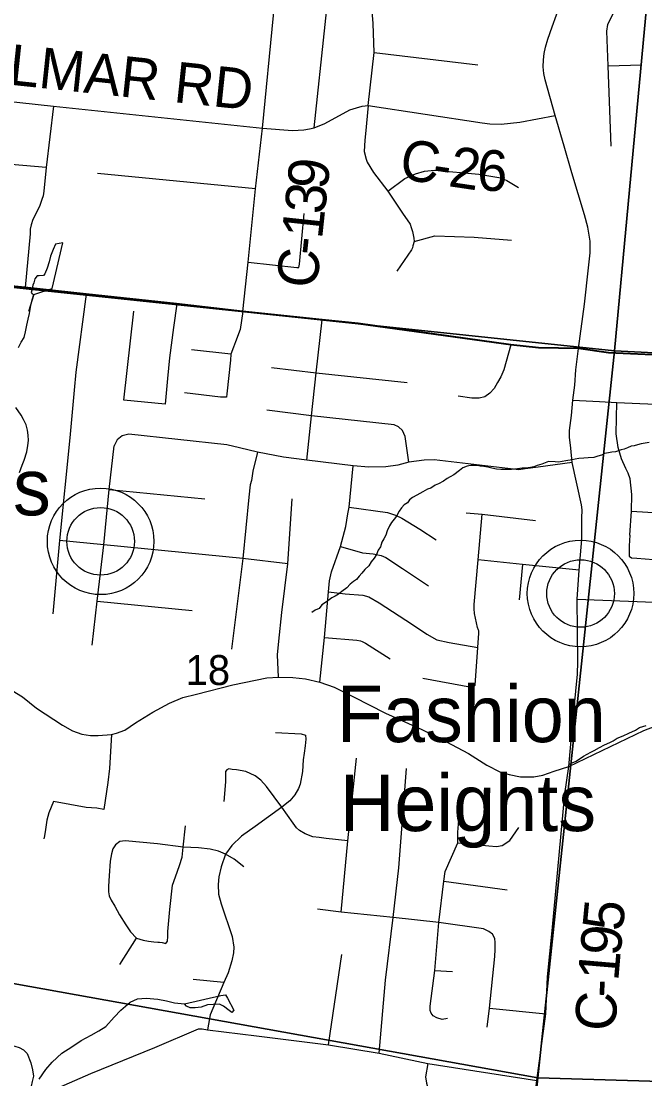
# Model space of a CAD drawing. Extents: x 0 to 34, y -2 to 22.
# Drawn here: x 4.421 to 5.292, y 16.731 to 18.207 of the extents above; entities that cross this region are included whole.
import ezdxf

# ---------------------------------------------------------------- set-up
doc = ezdxf.new("R2010")
doc.units = 0
for name, color, linetype in [('GM_X_City_Street', 7, 'Continuous'), ('GM_X_County_Road', 7, 'Continuous'), ('GM_X_County_Road_Text', 7, 'Continuous'), ('GM_X_Minor_Lake', 7, 'Continuous'), ('GM_X_Minor_River', 7, 'Continuous'), ('GM_X_Rail_Line', 7, 'Continuous'), ('GM_X_Section', 7, 'Continuous'), ('GM_X_Section_Text', 7, 'Continuous'), ('GM_X_Township_Road', 7, 'Continuous'), ('GM_X_Unincorporated', 7, 'Continuous'), ('GM_X_Unincorporated_Location', 7, 'Continuous'), ('GM_X_Unincorporated_Text', 7, 'Continuous')]:
    doc.layers.add(name, color=color, linetype=linetype)

msp = doc.modelspace()

# ---------------------------------------------------------------- linework, layer by layer
at = {"layer": 'GM_X_City_Street'}
for points in [[(5.2288, 17.6765), (5.2532, 17.6752), (5.3283, 17.6719), (5.3788, 17.6699), (5.4526, 17.667), (5.501, 17.6644), (5.5827, 17.6607), (5.6067, 17.6595)], [(5.2712, 17.4896), (5.2736, 17.5232), (5.2739, 17.5466), (5.2716, 17.5684), (5.2689, 17.5761), (5.2656, 17.5829), (5.2598, 17.5964), (5.2549, 17.612), (5.2519, 17.6313), (5.2525, 17.6536), (5.2532, 17.6752)], [(5.2736, 17.5232), (5.3959, 17.516), (5.5019, 17.5109), (5.6874, 17.5046)]]:
    msp.add_lwpolyline(points, dxfattribs=at)
at = {"layer": 'GM_X_County_Road'}
for points in [[(4.9058, 18.0895), (4.914, 18.1636), (4.9129, 18.2041), (4.9103, 18.2323), (4.9092, 18.2511), (4.912, 18.2992), (4.919, 18.3609), (4.9373, 18.5269), (4.9392, 18.5513), (4.9522, 18.681), (4.956, 18.7149), (4.96, 18.7468), (4.9616, 18.7789), (4.9603, 18.8074)], [(5.1995, 17.7504), (5.2081, 17.8122), (5.2137, 17.863), (5.2158, 17.884), (5.216, 17.9002), (5.2124, 17.92), (5.2081, 17.9372), (5.1901, 17.9956), (5.1796, 18.033), (5.167, 18.0759), (5.1529, 18.1255), (5.1513, 18.1344), (5.1502, 18.1437), (5.1505, 18.1536), (5.1514, 18.1624), (5.1532, 18.1709), (5.1565, 18.1821), (5.1626, 18.1996), (5.1689, 18.2162), (5.1837, 18.2512), (5.192, 18.2677), (5.2341, 18.3169), (5.2918, 18.3843)], [(4.758, 18.0581), (4.7735, 18.2155), (4.7827, 18.2933), (4.7846, 18.3009), (4.7878, 18.3085), (4.7947, 18.3207), (4.8069, 18.3317)], [(4.2476, 18.1125), (4.466, 18.0886), (4.758, 18.0581)], [(4.758, 18.0581), (4.8001, 18.0546), (4.816, 18.0555), (4.8238, 18.0571), (4.8301, 18.0586), (4.8453, 18.0645), (4.8802, 18.0835), (4.8892, 18.0864), (4.8974, 18.0886), (4.9058, 18.0895), (5.0649, 18.0655), (5.0755, 18.064), (5.0914, 18.0636), (5.1176, 18.0663), (5.167, 18.0759)], [(4.7305, 17.8021), (4.7381, 17.8709), (4.7482, 17.9732), (4.758, 18.0581)], [(3.699, 17.9089), (3.9116, 17.8892), (3.995, 17.8815), (4.2231, 17.8563), (4.3328, 17.8445), (4.4265, 17.8357), (4.5119, 17.8261), (4.6385, 17.8125), (4.7305, 17.8021), (4.8416, 17.7902), (4.8921, 17.785), (5.1052, 17.7555), (5.1438, 17.7513), (5.1995, 17.7504), (5.2414, 17.7441), (5.2926, 17.7419), (5.3775, 17.7381), (5.4364, 17.7355), (5.4969, 17.7336), (5.5492, 17.7321), (5.6317, 17.7272), (5.6868, 17.7254)], [(5.1858, 17.1668), (5.1915, 17.229), (5.1979, 17.2958), (5.1986, 17.3129), (5.1976, 17.4004), (5.2004, 17.4407), (5.2041, 17.4837), (5.2044, 17.5134), (5.2045, 17.5252), (5.2038, 17.532), (5.1906, 17.5912), (5.1887, 17.6112), (5.1871, 17.6265), (5.1871, 17.6358), (5.1897, 17.6567), (5.1918, 17.6782), (5.1945, 17.6994), (5.1958, 17.7208), (5.1995, 17.7504)], [(4.4086, 17.2728), (4.4228, 17.2642), (4.4422, 17.2482), (4.4788, 17.2243), (4.4927, 17.2164), (4.5058, 17.2119), (4.5179, 17.2102), (4.5286, 17.2099), (4.547, 17.2114), (4.5544, 17.2132), (4.5659, 17.2175), (4.5809, 17.2278), (4.6051, 17.2428), (4.6282, 17.2552), (4.6469, 17.2631), (4.666, 17.2676), (4.7167, 17.281), (4.7643, 17.2905), (4.7805, 17.2916), (4.8003, 17.291), (4.8183, 17.2893), (4.838, 17.2847), (4.858, 17.2774), (4.8853, 17.2641), (4.9297, 17.2414), (4.9809, 17.2185), (5.0143, 17.2017), (5.046, 17.185), (5.0717, 17.1687), (5.0897, 17.1591), (5.1025, 17.1557), (5.1183, 17.1523), (5.1369, 17.1525), (5.1499, 17.1548), (5.1656, 17.1601), (5.1858, 17.1668), (5.2909, 17.2169), (5.3286, 17.2315)], [(5.075, 16.1095), (5.0801, 16.1592), (5.0864, 16.2182), (5.0917, 16.2685), (5.1105, 16.4445), (5.1137, 16.4765), (5.125, 16.5888), (5.1259, 16.5986), (5.1413, 16.7282), (5.1541, 16.8214), (5.1564, 16.873), (5.1627, 16.9374), (5.1803, 17.1286), (5.1858, 17.1668)], [(4.4407, 16.704), (4.5182, 16.7383), (4.6077, 16.7743), (4.6686, 16.8003), (4.6699, 16.8007), (4.6712, 16.8007), (4.6737, 16.8004), (4.6815, 16.7989), (4.7498, 16.7906), (4.8504, 16.7781), (4.9209, 16.7667), (4.9892, 16.752), (5.1413, 16.7282)]]:
    msp.add_lwpolyline(points, dxfattribs=at)
at = {"layer": 'GM_X_Minor_Lake'}
for points in [[(4.4387, 17.8257), (4.4643, 17.8343), (4.4793, 17.8977), (4.469, 17.8961), (4.4658, 17.8886), (4.4621, 17.8792), (4.46, 17.8716), (4.4575, 17.8626), (4.4542, 17.8547), (4.4523, 17.8525), (4.4462, 17.8519), (4.4432, 17.852), (4.44, 17.8475), (4.4387, 17.8422), (4.4375, 17.8388)], [(4.4375, 17.8388), (4.4362, 17.8347), (4.4357, 17.832), (4.435, 17.8286), (4.4362, 17.8268), (4.4387, 17.8257)], [(4.6491, 16.8352), (4.7, 16.8469), (4.7065, 16.8482), (4.7094, 16.8432), (4.7181, 16.8266), (4.7153, 16.8233), (4.7116, 16.8261), (4.7038, 16.8323), (4.6982, 16.8348), (4.6894, 16.8346), (4.6811, 16.8341), (4.6726, 16.8309)], [(4.6726, 16.8309), (4.6639, 16.8296), (4.657, 16.8298), (4.6518, 16.8322), (4.6491, 16.8352)]]:
    msp.add_lwpolyline(points, dxfattribs=at)
at = {"layer": 'GM_X_Minor_River'}
for points in [[(4.4171, 17.7516), (4.4211, 17.7591), (4.425, 17.7655), (4.4271, 17.7738), (4.4288, 17.7829), (4.4309, 17.7912), (4.4325, 17.7992), (4.4346, 17.8102), (4.4363, 17.8181), (4.4387, 17.8257), (4.4314, 17.8022)], [(4.4185, 17.5771), (4.4225, 17.5873), (4.4254, 17.5944), (4.429, 17.6061), (4.4303, 17.6149), (4.4312, 17.6221), (4.431, 17.6293), (4.4299, 17.6362), (4.4282, 17.6438), (4.4245, 17.6511), (4.4211, 17.6572), (4.4137, 17.668)], [(5.298, 17.6191), (5.2869, 17.6171), (5.282, 17.6161), (5.2774, 17.6147), (5.2732, 17.6141), (5.2678, 17.6116), (5.2635, 17.6098), (5.2589, 17.6088), (5.2513, 17.606), (5.2459, 17.6057), (5.2413, 17.6047), (5.236, 17.6037), (5.2318, 17.6015), (5.2264, 17.6002), (5.221, 17.5984), (5.213, 17.5975), (5.2069, 17.5973), (5.2001, 17.5967), (5.1947, 17.5957), (5.1905, 17.5951), (5.1817, 17.5934), (5.1767, 17.5924), (5.1718, 17.5918), (5.1669, 17.5923), (5.1574, 17.5926), (5.1481, 17.589), (5.142, 17.5869), (5.137, 17.5851), (5.1324, 17.5841), (5.1255, 17.5832), (5.121, 17.5833), (5.1141, 17.5824), (5.1099, 17.5821), (5.1057, 17.5815), (5.1004, 17.5816), (5.0951, 17.5814), (5.0909, 17.5815), (5.0848, 17.582), (5.0784, 17.5834), (5.0727, 17.5847), (5.0674, 17.5856), (5.0621, 17.5861), (5.0579, 17.587), (5.0538, 17.5871), (5.0488, 17.5869), (5.0439, 17.5862), (5.0381, 17.5837), (5.0334, 17.58), (5.0253, 17.5742), (5.0203, 17.5713), (5.016, 17.5687), (5.011, 17.5651), (5.004, 17.5614), (4.9994, 17.5597), (4.9932, 17.5556), (4.9886, 17.5539), (4.982, 17.5502), (4.9778, 17.5477), (4.9735, 17.5455), (4.9677, 17.5423), (4.9635, 17.5393), (4.9607, 17.5348), (4.9561, 17.5319), (4.9525, 17.5278), (4.949, 17.5234), (4.9454, 17.5162), (4.9418, 17.5121), (4.9383, 17.5073), (4.9355, 17.5028), (4.9323, 17.496), (4.9302, 17.4896), (4.9274, 17.4847), (4.925, 17.4799), (4.9229, 17.4734), (4.9197, 17.469), (4.9173, 17.4626), (4.9141, 17.4577), (4.9098, 17.4525), (4.9066, 17.4469), (4.9011, 17.4417), (4.8968, 17.4368), (4.8933, 17.4324), (4.8893, 17.4279), (4.8851, 17.425), (4.8804, 17.4213), (4.8757, 17.4161), (4.8691, 17.4113), (4.8641, 17.4073), (4.8598, 17.4047), (4.8548, 17.4022), (4.8474, 17.3967), (4.8412, 17.3923), (4.8373, 17.3875), (4.8319, 17.385), (4.8269, 17.382)], [(5.1862, 17.1694), (5.1908, 17.1719), (5.1962, 17.174), (5.2067, 17.181), (5.2167, 17.1868), (5.2213, 17.1893), (5.229, 17.1933), (5.236, 17.1969), (5.2433, 17.2005), (5.2479, 17.2027), (5.2534, 17.2063), (5.2618, 17.2095), (5.2699, 17.2131), (5.2791, 17.2174), (5.2849, 17.2211), (5.2941, 17.2239)], [(4.446, 16.7302), (4.4555, 16.7436), (4.4645, 16.754), (4.4777, 16.7666), (4.4916, 16.7754), (4.5047, 16.7842), (4.5186, 16.7918), (4.5297, 16.7976), (4.5394, 16.8038), (4.5507, 16.8168), (4.56, 16.8265), (4.5732, 16.8379), (4.5836, 16.8422), (4.5954, 16.8431), (4.6121, 16.8419), (4.6238, 16.8397), (4.6351, 16.8367), (4.6491, 16.8352)]]:
    msp.add_lwpolyline(points, dxfattribs=at)
at = {"layer": 'GM_X_Rail_Line'}
for points in [[(6.0414, 17.7045), (5.905, 17.7117), (5.8721, 17.714), (5.7046, 17.7254), (5.6315, 17.7277), (5.5489, 17.7326), (5.4967, 17.7342), (5.4361, 17.736), (5.3773, 17.7386), (5.2924, 17.7424), (5.2412, 17.7447), (5.1993, 17.7509), (5.1435, 17.7518), (5.105, 17.756), (4.8918, 17.7856), (4.8414, 17.7907), (4.7302, 17.8027), (4.6382, 17.813), (4.5117, 17.8266), (4.4263, 17.8362), (4.3326, 17.8451)], [(4.3326, 17.8451), (4.4263, 17.8362), (4.5117, 17.8266), (4.6382, 17.813), (4.7302, 17.8027), (4.8414, 17.7907), (4.8918, 17.7856), (5.105, 17.756), (5.1435, 17.7518), (5.1993, 17.7509), (5.2412, 17.7447), (5.2924, 17.7424), (5.3773, 17.7386), (5.4361, 17.736), (5.4967, 17.7342), (5.5489, 17.7326), (5.6315, 17.7277), (5.7046, 17.7254), (5.8721, 17.714), (5.905, 17.7117), (6.0414, 17.7045)]]:
    msp.add_lwpolyline(points, dxfattribs=at)
at = {"layer": 'GM_X_Section'}
for points in [[(4.3356, 18.8839), (5.3451, 18.7715), (5.25, 17.7471), (4.2197, 17.8557)], [(6.3407, 18.6907), (6.241, 17.6971), (5.25, 17.7471), (5.3451, 18.7715)], [(5.25, 17.7471), (5.1427, 16.732), (4.1192, 16.9159), (4.2197, 17.8557)], [(5.25, 17.7471), (6.241, 17.6971), (6.1288, 16.703), (5.1427, 16.732)], [(5.1427, 16.732), (5.0363, 15.7105), (4.012, 15.9002), (4.1192, 16.9159)], [(6.1288, 16.703), (6.0281, 15.6802), (5.0363, 15.7105), (5.1427, 16.732)]]:
    msp.add_lwpolyline(points, close=True, dxfattribs=at)
at = {"layer": 'GM_X_Township_Road'}
for p, q in [((4.914, 18.1636), (5.0589, 18.1463)), ((5.2407, 18.1449), (5.2879, 18.1463)), ((4.9058, 18.0895), (4.9019, 18.0501)), ((4.7482, 17.9732), (4.5275, 17.9949)), ((4.7137, 17.7426), (4.6588, 17.7483)), ((5.1918, 17.6782), (5.2288, 17.6765)), ((4.544, 17.5535), (4.6774, 17.5403)), ((5.1212, 17.4487), (5.1165, 17.3994)), ((4.5274, 17.3978), (4.6597, 17.3848)), ((5.1976, 17.4004), (5.3051, 17.3963)), ((5.0112, 17.0066), (5.1, 16.9947)), ((4.5587, 16.8903), (4.5821, 16.9272)), ((4.8504, 16.7781), (4.8688, 16.9043)), ((4.999, 16.8819), (5.0233, 16.8807)), ((4.7042, 16.8653), (4.6611, 16.8696)), ((5.0753, 16.8292), (5.1541, 16.8214))]:
    msp.add_line(p, q, dxfattribs=at)
for points in [[(4.8301, 18.0586), (4.8458, 18.2029), (4.8498, 18.2432), (4.8495, 18.253), (4.8486, 18.2621), (4.8456, 18.2771), (4.8379, 18.3106)], [(5.6331, 18.147), (5.5728, 18.1695), (5.5272, 18.1857), (5.5195, 18.1902), (5.5138, 18.1951), (5.5105, 18.2027), (5.5098, 18.2126), (5.5107, 18.2244), (5.514, 18.255), (5.5122, 18.2628), (5.5089, 18.2677), (5.5041, 18.2723), (5.4968, 18.2756), (5.4906, 18.2768), (5.2927, 18.2891), (5.2844, 18.2867), (5.2781, 18.2824), (5.274, 18.2749), (5.2571, 18.2366), (5.2399, 18.2026), (5.2384, 18.1933), (5.2407, 18.1449), (5.2446, 18.0329)], [(4.466, 18.0886), (4.4557, 18.0029), (4.4527, 17.97), (4.4516, 17.9637), (4.4498, 17.9584), (4.4465, 17.9488), (4.4374, 17.9305), (4.4349, 17.9228), (4.4338, 17.9169), (4.4334, 17.9105), (4.4265, 17.8357)], [(4.9019, 18.0501), (4.9011, 18.0413), (4.9002, 18.0253), (4.9028, 18.0145), (4.9041, 18.0104), (4.9132, 17.9961), (4.9331, 17.97), (4.95, 17.945)], [(4.4557, 18.0029), (4.4071, 18.0073), (4.3964, 18.0107), (4.3822, 18.0151), (4.3409, 18.0285), (4.3126, 18.0377), (4.2853, 18.0414), (4.2406, 18.0456)], [(4.9331, 17.97), (4.9567, 17.9878), (4.972, 17.9941), (4.9846, 17.9979), (4.9983, 17.9995), (5.0602, 17.9937), (5.0908, 17.9887), (5.0994, 17.985), (5.1158, 17.9751)], [(4.95, 17.945), (4.9539, 17.9392), (4.9642, 17.9241), (4.966, 17.9191), (4.9678, 17.9135), (4.9696, 17.9044), (4.9698, 17.8996), (4.9683, 17.8938), (4.9676, 17.8908), (4.9662, 17.8883), (4.9459, 17.8583)], [(4.7381, 17.8709), (4.8061, 17.8634), (4.809, 17.8633), (4.8097, 17.8679), (4.8164, 17.9387)], [(4.9698, 17.8996), (4.9988, 17.9077), (5.0536, 17.9059), (5.1057, 17.9015)], [(4.5119, 17.8261), (4.4976, 17.7173), (4.4952, 17.6923), (4.4888, 17.6257), (4.4746, 17.4821), (4.4651, 17.38)], [(4.6385, 17.8125), (4.6337, 17.7795), (4.628, 17.7375), (4.6256, 17.7086), (4.6222, 17.6726), (4.5643, 17.6782), (4.5783, 17.8027)], [(4.7305, 17.8021), (4.7269, 17.7771), (4.7204, 17.7595), (4.7174, 17.7521), (4.7137, 17.7426), (4.7134, 17.7342), (4.7085, 17.6869), (4.708, 17.6822), (4.6995, 17.6825), (4.6491, 17.6883)], [(4.82, 17.5945), (4.8267, 17.6563), (4.8333, 17.7165), (4.8416, 17.7902)], [(5.1052, 17.7555), (5.0952, 17.7204), (5.0908, 17.7106), (5.0864, 17.703), (5.0815, 17.6947), (5.0758, 17.6882), (5.0686, 17.6829), (5.0608, 17.681), (5.0506, 17.681), (5.0312, 17.6838)], [(4.7705, 17.7239), (4.8333, 17.7165), (4.96, 17.7027)], [(4.9626, 17.5915), (4.9573, 17.6276), (4.9536, 17.6357), (4.9479, 17.6408), (4.9418, 17.644), (4.8267, 17.6563), (4.7641, 17.6642)], [(5.1906, 17.5912), (5.1433, 17.5849), (5.1251, 17.5822), (5.1161, 17.5809), (5.1085, 17.5817), (4.9977, 17.5947), (4.984, 17.5944), (4.9626, 17.5915), (4.9471, 17.5874), (4.9303, 17.5851), (4.9068, 17.5846), (4.8849, 17.5865), (4.82, 17.5945), (4.7874, 17.5987), (4.7509, 17.6057), (4.7261, 17.6115), (4.7082, 17.6157), (4.5715, 17.6307), (4.5619, 17.6283), (4.5553, 17.6228), (4.5507, 17.6146)], [(4.5203, 17.336), (4.5274, 17.3978), (4.5363, 17.4762), (4.544, 17.5535), (4.5507, 17.6146)], [(4.7509, 17.6057), (4.7448, 17.5791), (4.7426, 17.5663), (4.7411, 17.5601), (4.7392, 17.5429), (4.7305, 17.4572), (4.7148, 17.3307)], [(4.838, 17.2847), (4.8449, 17.347), (4.8505, 17.4105), (4.8519, 17.4262), (4.8544, 17.4386), (4.867, 17.4738), (4.8743, 17.5017), (4.8774, 17.5194), (4.8792, 17.5287), (4.8849, 17.5865)], [(4.7805, 17.2916), (4.7791, 17.3229), (4.7809, 17.3416), (4.7849, 17.382), (4.7934, 17.4499), (4.7994, 17.5404)], [(4.8792, 17.5287), (4.9326, 17.5213), (4.9437, 17.5178), (4.9528, 17.5134), (4.9778, 17.4979), (5.0009, 17.4834)], [(4.982, 17.2903), (5.0499, 17.2775), (5.0517, 17.2776), (5.0534, 17.2781), (5.0544, 17.2792), (5.055, 17.2804), (5.0588, 17.3327), (5.0603, 17.3531), (5.0603, 17.3551), (5.0603, 17.3563), (5.06, 17.3573), (5.0585, 17.361), (5.0542, 17.3802), (5.0537, 17.387), (5.054, 17.393), (5.0594, 17.4551), (5.0648, 17.5191)], [(5.0428, 17.521), (5.0648, 17.5191), (5.1395, 17.51)], [(5.2712, 17.4896), (5.2702, 17.4749), (5.2701, 17.4683), (5.2704, 17.4604), (5.2737, 17.4582), (5.2811, 17.4575), (5.3157, 17.4548)], [(4.7934, 17.4499), (4.7305, 17.4572), (4.5363, 17.4762), (4.4746, 17.4821)], [(4.867, 17.4738), (4.8977, 17.465), (4.9127, 17.4635), (4.9238, 17.4612), (4.9302, 17.4586), (4.9539, 17.4432), (4.99, 17.4188)], [(5.2004, 17.4407), (5.1212, 17.4487), (5.0594, 17.4551)], [(4.8505, 17.4105), (4.8736, 17.4079), (4.8983, 17.406), (4.9068, 17.4035), (4.921, 17.3952), (4.9678, 17.3649), (4.9876, 17.3516), (5.0018, 17.3438), (5.0188, 17.34), (5.0588, 17.3327)], [(4.8449, 17.347), (4.8898, 17.343), (4.8948, 17.3422), (4.8975, 17.3414), (4.9019, 17.339), (4.9364, 17.3171)], [(4.547, 17.2114), (4.5444, 17.1641), (4.5422, 17.1446), (4.5365, 17.1065), (4.5266, 17.1086), (4.512, 17.1093), (4.4661, 17.1179), (4.4596, 17.1019), (4.4567, 17.0918), (4.4552, 17.0787), (4.4538, 17.07), (4.4525, 17.0657)], [(4.7763, 17.2141), (4.8123, 17.2123), (4.818, 17.2107), (4.8188, 17.2047), (4.8177, 17.1956), (4.8164, 17.1852), (4.8151, 17.1763), (4.8141, 17.1596), (4.8107, 17.1421), (4.8085, 17.1362), (4.8035, 17.1274), (4.7965, 17.1186), (4.7852, 17.1101), (4.7479, 17.0828), (4.729, 17.0694), (4.7155, 17.0565), (4.7065, 17.0446), (4.7004, 17.0269), (4.6971, 17.0125), (4.6962, 17.0019), (4.6966, 16.9886), (4.7005, 16.9752), (4.7158, 16.9294), (4.7179, 16.9145), (4.7176, 16.9066), (4.7151, 16.8956), (4.7102, 16.8787), (4.7042, 16.8653), (4.685, 16.8201), (4.6815, 16.7989)], [(4.8678, 16.9636), (4.8771, 17.0632), (4.8893, 17.1782)], [(4.8372, 17.0676), (4.8284, 17.0687), (4.8176, 17.0726), (4.8097, 17.0776), (4.8058, 17.0812), (4.801, 17.0876), (4.7852, 17.1101), (4.7635, 17.1388), (4.7558, 17.1477), (4.7479, 17.1536), (4.735, 17.1596), (4.7218, 17.1621), (4.7156, 17.1627), (4.7111, 17.1633), (4.7082, 17.1623), (4.7065, 17.16), (4.7066, 17.1555), (4.7066, 17.1452), (4.704, 17.1179)], [(4.9209, 16.7667), (4.9298, 16.8685), (4.9406, 16.9558), (4.9486, 17.0251), (4.9593, 17.1641)], [(5.0166, 16.815), (5.009, 16.8136), (5.0017, 16.8159), (4.9967, 16.8187), (4.9937, 16.8222), (4.9921, 16.8261), (4.9924, 16.8322), (4.999, 16.8819), (5.0046, 16.9488), (5.0112, 17.0066), (5.0132, 17.0202), (5.0308, 17.0604), (5.031, 17.075), (5.0336, 17.1086)], [(4.6144, 16.9213), (4.618, 16.9211), (4.6231, 16.9197), (4.6254, 16.9227), (4.626, 16.9296), (4.6261, 16.9366), (4.6289, 16.9672), (4.6324, 17.001), (4.6365, 17.0128), (4.6424, 17.0284), (4.6461, 17.0402), (4.6474, 17.0543), (4.6505, 17.0839)], [(5.0308, 17.0604), (5.0742, 17.056), (5.0851, 17.0549), (5.0931, 17.0563), (5.1034, 17.0634), (5.1164, 17.0818)], [(4.7322, 17.0266), (4.7187, 17.0372), (4.7065, 17.0446), (4.6966, 17.0487), (4.6848, 17.0513), (4.6685, 17.053), (4.6474, 17.0543), (4.6113, 17.0587), (4.5662, 17.0632), (4.5588, 17.062), (4.5529, 17.0574), (4.5492, 17.0517), (4.5473, 17.0449), (4.5455, 17.0347), (4.544, 17.0141), (4.5428, 16.9995), (4.5429, 16.9917), (4.5441, 16.9862), (4.5467, 16.9803), (4.5517, 16.9719), (4.5585, 16.9598), (4.5673, 16.9456), (4.5738, 16.9358), (4.5821, 16.9272), (4.5915, 16.9242), (4.5989, 16.923), (4.6062, 16.922), (4.6117, 16.9216), (4.6144, 16.9213)], [(4.8771, 17.0632), (4.847, 17.0664), (4.8372, 17.0676)], [(5.0718, 16.8028), (5.0753, 16.8292), (5.0826, 16.9013), (5.0829, 16.9111), (5.0833, 16.917), (5.0833, 16.9209), (5.0826, 16.9264), (5.0794, 16.9325), (5.0744, 16.9366), (5.0669, 16.9401), (5.0046, 16.9488), (4.9406, 16.9558), (4.8678, 16.9636), (4.8351, 16.9675)], [(4.3447, 16.7881), (4.3507, 16.7865), (4.3557, 16.7854), (4.3649, 16.7846), (4.3847, 16.7811), (4.4005, 16.7784), (4.4121, 16.7762), (4.4182, 16.7743), (4.4244, 16.7712), (4.4292, 16.7661), (4.4344, 16.753), (4.4369, 16.7431), (4.4384, 16.7346), (4.4364, 16.7269), (4.4351, 16.7205), (4.4358, 16.7122), (4.4382, 16.7085), (4.4407, 16.704)], [(4.9892, 16.752), (4.9856, 16.7334), (4.9874, 16.7247), (4.9899, 16.7145), (4.9936, 16.7038), (4.9966, 16.6923), (4.9995, 16.6846), (4.9997, 16.6757), (4.9986, 16.6658), (4.998, 16.6587)]]:
    msp.add_lwpolyline(points, dxfattribs=at)
at = {"layer": 'GM_X_Unincorporated'}
for centre, radius in [((4.532, 17.4811), 0.0744), ((4.532, 17.4811), 0.0472), ((5.2024, 17.4083), 0.0744), ((5.2024, 17.4083), 0.0472)]:
    msp.add_circle(centre, radius, dxfattribs=at)
at = {"layer": 'GM_X_Unincorporated_Location'}
for p, q in [((4.532, 17.4811), (4.532, 17.4811)), ((5.2024, 17.4083), (5.2024, 17.4083))]:
    msp.add_line(p, q, dxfattribs=at)

# ---------------------------------------------------------------- texts
at = {"layer": 'GM_X_County_Road_Text'}
for s, height, rotation, p in [('JULMAR RD', 0.05682, 353.9278, (4.3096, 18.1289)), ('C', 0.0568, 351.4274, (4.9476, 17.9875)), ('2', 0.0568, 351.5516, (5.0164, 17.9772)), ('6', 0.0568, 357.2843, (5.0569, 17.9715)), ('9', 0.0568, 83.9194, (4.8487, 17.9711)), ('-', 0.0568, 351.4431, (4.9934, 17.9806)), ('3', 0.0568, 83.887, (4.845, 17.9365)), ('1', 0.0568, 83.8692, (4.8412, 17.902)), ('-', 0.0568, 83.8662, (4.8388, 17.879)), ('C', 0.0568, 83.866, (4.8338, 17.8329)), ('5', 0.0568, 84.4675, (5.2613, 16.9357)), ('9', 0.0568, 84.5851, (5.258, 16.9009)), ('1', 0.0568, 85.1311, (5.255, 16.8662)), ('-', 0.0568, 87.0448, (5.2538, 16.8434)), ('C', 0.0568, 86.4616, (5.2509, 16.7962))]:
    msp.add_text(s, height=height, rotation=rotation, dxfattribs=at).set_placement(p)
at = {"layer": 'GM_X_Section_Text'}
msp.add_text('18', height=0.04186, rotation=0, dxfattribs=at).set_placement((4.6506, 17.2805))
at = {"layer": 'GM_X_Unincorporated_Text'}
for s, p in [('The Pines', (3.9869, 17.5175)), ('Fashion', (4.8619, 17.2008)), ('Heights', (4.866, 17.0766))]:
    msp.add_text(s, height=0.07898, rotation=0, dxfattribs=at).set_placement(p)

doc.saveas('drawing.dxf')
